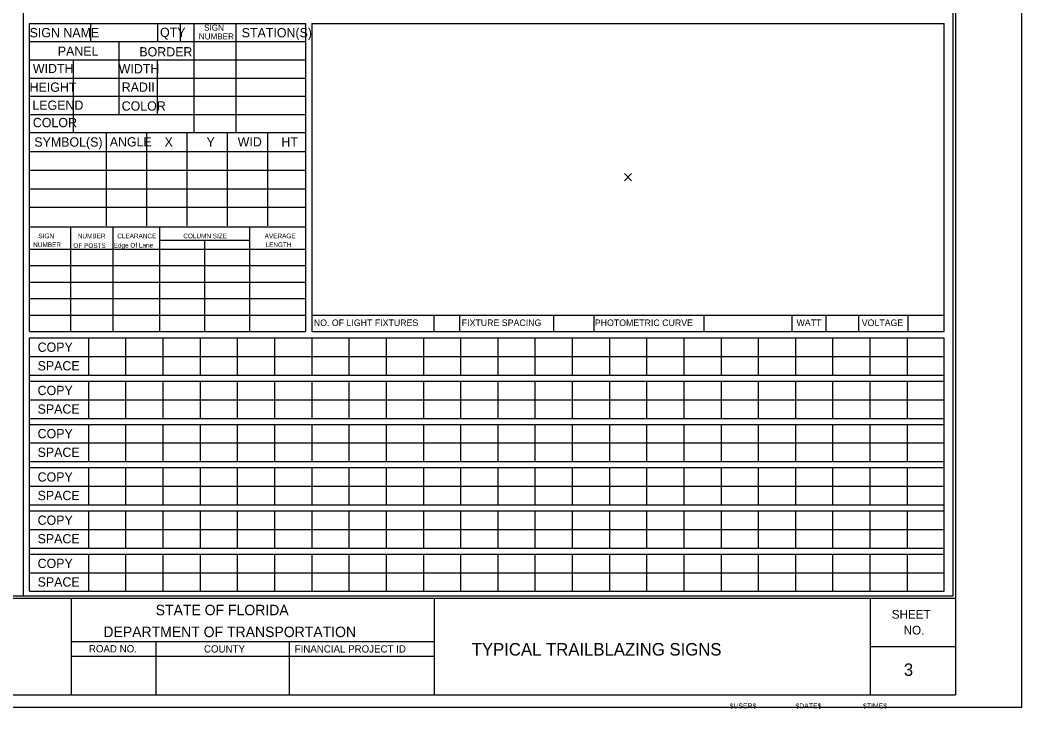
# Model space of a CAD drawing. Extents: x 17890628 to 17890754, y 17897693 to 17897992.
# Drawn here: x 17890707.16 to 17890727.42, y 17897874.78 to 17897888.7 of the extents above; entities that cross this region are included whole.
import ezdxf

# ---------------------------------------------------------------- set-up
doc = ezdxf.new("R2010")
doc.units = 0
for name, color, linetype in [('NonPlottingEle_dp', 7, 'Continuous'), ('PlotBorder_dp', 7, 'Continuous'), ('SheetBorder_dp', 7, 'Continuous'), ('SheetLines_dp', 7, 'Continuous'), ('SheetLinesMisc2_dp', 7, 'Continuous'), ('TextMinor', 7, 'Continuous'), ('TextMisc', 7, 'Continuous')]:
    doc.layers.add(name, color=color, linetype=linetype)

msp = doc.modelspace()

# ---------------------------------------------------------------- linework, layer by layer
at = {"layer": 'NonPlottingEle_dp'}
for p, q in [((17890719.378, 17897885.597), (17890719.524, 17897885.451)), ((17890719.378, 17897885.451), (17890719.524, 17897885.597))]:
    msp.add_line(p, q, dxfattribs=at)
at = {"layer": 'PlotBorder_dp'}
msp.add_lwpolyline([(17890687.002, 17897874.814), (17890727.417, 17897874.814), (17890727.417, 17897900.777), (17890687.002, 17897900.777)], close=True, dxfattribs=at)
at = {"layer": 'SheetBorder_dp'}
for p, q in [((17890726.07, 17897900.533), (17890726.07, 17897875.059)), ((17890688.35, 17897877.018), (17890726.07, 17897877.018)), ((17890688.35, 17897875.059), (17890726.07, 17897875.059))]:
    msp.add_line(p, q, dxfattribs=at)
at = {"layer": 'SheetLines_dp'}
for p, q in [((17890708.19, 17897877.018), (17890708.19, 17897875.059)), ((17890715.538, 17897875.059), (17890715.538, 17897877.018)), ((17890724.356, 17897875.059), (17890724.356, 17897877.018)), ((17890708.19, 17897876.137), (17890715.538, 17897876.137)), ((17890709.904, 17897876.137), (17890709.904, 17897875.059)), ((17890712.598, 17897876.137), (17890712.598, 17897875.059)), ((17890724.356, 17897876.039), (17890726.07, 17897876.039)), ((17890708.19, 17897875.843), (17890715.538, 17897875.843))]:
    msp.add_line(p, q, dxfattribs=at)
at = {"layer": 'SheetLinesMisc2_dp'}
for p, q in [((17890707.222, 17897900.475), (17890707.222, 17897877.063)), ((17890726.026, 17897877.063), (17890726.026, 17897900.474)), ((17890707.351, 17897882.404), (17890707.351, 17897888.634)), ((17890707.351, 17897888.634), (17890712.927, 17897888.634)), ((17890708.58, 17897888.634), (17890708.58, 17897888.266)), ((17890709.935, 17897888.634), (17890709.935, 17897888.266)), ((17890710.398, 17897888.634), (17890710.398, 17897888.266)), ((17890710.674, 17897888.634), (17890710.674, 17897886.426)), ((17890711.523, 17897888.634), (17890711.523, 17897886.426)), ((17890712.927, 17897888.634), (17890712.927, 17897882.404)), ((17890713.055, 17897888.634), (17890725.847, 17897888.634)), ((17890713.055, 17897888.634), (17890713.055, 17897882.413)), ((17890725.847, 17897882.413), (17890725.847, 17897888.635)), ((17890707.351, 17897888.266), (17890712.927, 17897888.266)), ((17890709.153, 17897888.266), (17890709.153, 17897886.79)), ((17890707.351, 17897887.898), (17890712.927, 17897887.898)), ((17890708.232, 17897887.898), (17890708.232, 17897886.426)), ((17890709.931, 17897887.894), (17890709.931, 17897886.79)), ((17890707.351, 17897887.53), (17890712.927, 17897887.53)), ((17890707.351, 17897887.162), (17890712.927, 17897887.162)), ((17890707.351, 17897886.794), (17890709.419, 17897886.794)), ((17890709.153, 17897886.79), (17890710.674, 17897886.79)), ((17890710.674, 17897886.794), (17890712.927, 17897886.794)), ((17890707.351, 17897886.426), (17890712.927, 17897886.426)), ((17890708.899, 17897886.419), (17890708.899, 17897884.54)), ((17890709.714, 17897886.419), (17890709.714, 17897884.54)), ((17890710.529, 17897886.419), (17890710.529, 17897884.54)), ((17890711.344, 17897886.419), (17890711.344, 17897884.54)), ((17890712.159, 17897886.419), (17890712.159, 17897884.54)), ((17890707.352, 17897886.043), (17890712.927, 17897886.043)), ((17890707.352, 17897885.667), (17890712.927, 17897885.667)), ((17890707.352, 17897885.292), (17890712.927, 17897885.292)), ((17890707.352, 17897884.916), (17890712.927, 17897884.916)), ((17890707.351, 17897884.522), (17890712.927, 17897884.522)), ((17890708.178, 17897884.522), (17890708.178, 17897882.404)), ((17890709.033, 17897884.522), (17890709.033, 17897882.404)), ((17890709.978, 17897884.522), (17890709.978, 17897882.404)), ((17890711.796, 17897884.522), (17890711.796, 17897882.404)), ((17890709.978, 17897884.253), (17890711.795, 17897884.253)), ((17890710.891, 17897884.253), (17890710.891, 17897882.404)), ((17890707.351, 17897884.073), (17890712.927, 17897884.073)), ((17890707.351, 17897883.739), (17890712.927, 17897883.739)), ((17890707.351, 17897883.405), (17890712.927, 17897883.405)), ((17890707.351, 17897883.071), (17890712.927, 17897883.071)), ((17890707.351, 17897882.738), (17890712.927, 17897882.738)), ((17890713.055, 17897882.738), (17890725.847, 17897882.738)), ((17890715.526, 17897882.738), (17890715.526, 17897882.404)), ((17890716.044, 17897882.738), (17890716.044, 17897882.404)), ((17890717.948, 17897882.738), (17890717.948, 17897882.404)), ((17890718.759, 17897882.738), (17890718.759, 17897882.404)), ((17890720.986, 17897882.738), (17890720.986, 17897882.404)), ((17890722.764, 17897882.738), (17890722.764, 17897882.404)), ((17890723.45, 17897882.738), (17890723.45, 17897882.404)), ((17890724.112, 17897882.738), (17890724.112, 17897882.404)), ((17890725.108, 17897882.738), (17890725.108, 17897882.404)), ((17890707.351, 17897882.404), (17890712.927, 17897882.404)), ((17890713.055, 17897882.413), (17890713.055, 17897882.404)), ((17890713.055, 17897882.404), (17890725.847, 17897882.404)), ((17890725.847, 17897882.404), (17890725.847, 17897882.413)), ((17890707.35, 17897882.276), (17890725.847, 17897882.276)), ((17890707.35, 17897877.154), (17890707.35, 17897882.276)), ((17890708.541, 17897882.276), (17890708.541, 17897881.524)), ((17890709.293, 17897882.276), (17890709.293, 17897881.524)), ((17890710.046, 17897882.276), (17890710.046, 17897881.524)), ((17890710.798, 17897882.276), (17890710.798, 17897881.524)), ((17890711.551, 17897882.276), (17890711.551, 17897881.524)), ((17890712.303, 17897882.276), (17890712.303, 17897881.524)), ((17890713.055, 17897882.276), (17890713.055, 17897881.524)), ((17890713.808, 17897882.276), (17890713.808, 17897881.524)), ((17890714.56, 17897882.276), (17890714.56, 17897881.524)), ((17890715.313, 17897882.276), (17890715.313, 17897881.524)), ((17890716.065, 17897882.276), (17890716.065, 17897881.524)), ((17890716.817, 17897882.276), (17890716.817, 17897881.524)), ((17890717.57, 17897882.276), (17890717.57, 17897881.524)), ((17890718.322, 17897882.276), (17890718.322, 17897881.524)), ((17890719.075, 17897882.276), (17890719.075, 17897881.524)), ((17890719.827, 17897882.276), (17890719.827, 17897881.524)), ((17890720.58, 17897882.276), (17890720.58, 17897881.524)), ((17890721.332, 17897882.276), (17890721.332, 17897881.524)), ((17890722.084, 17897882.276), (17890722.084, 17897881.524)), ((17890722.837, 17897882.276), (17890722.837, 17897881.524)), ((17890723.589, 17897882.276), (17890723.589, 17897881.524)), ((17890724.342, 17897882.276), (17890724.342, 17897881.524)), ((17890725.094, 17897882.276), (17890725.094, 17897881.524)), ((17890725.847, 17897877.154), (17890725.847, 17897882.276)), ((17890707.35, 17897881.9), (17890725.847, 17897881.9)), ((17890707.35, 17897881.524), (17890725.847, 17897881.524)), ((17890707.35, 17897881.402), (17890725.847, 17897881.402)), ((17890708.541, 17897881.402), (17890708.541, 17897880.65)), ((17890709.293, 17897881.402), (17890709.293, 17897880.65)), ((17890710.046, 17897881.402), (17890710.046, 17897880.65)), ((17890710.798, 17897881.402), (17890710.798, 17897880.65)), ((17890711.551, 17897881.402), (17890711.551, 17897880.65)), ((17890712.303, 17897881.402), (17890712.303, 17897880.65)), ((17890713.055, 17897881.402), (17890713.055, 17897880.65)), ((17890713.808, 17897881.402), (17890713.808, 17897880.65)), ((17890714.56, 17897881.402), (17890714.56, 17897880.65)), ((17890715.313, 17897881.402), (17890715.313, 17897880.65)), ((17890716.065, 17897881.402), (17890716.065, 17897880.65)), ((17890716.817, 17897881.402), (17890716.817, 17897880.65)), ((17890717.57, 17897881.402), (17890717.57, 17897880.65)), ((17890718.322, 17897881.402), (17890718.322, 17897880.65)), ((17890719.075, 17897881.402), (17890719.075, 17897880.65)), ((17890719.827, 17897881.402), (17890719.827, 17897880.65)), ((17890720.58, 17897881.402), (17890720.58, 17897880.65)), ((17890721.332, 17897881.402), (17890721.332, 17897880.65)), ((17890722.084, 17897881.402), (17890722.084, 17897880.65)), ((17890722.837, 17897881.402), (17890722.837, 17897880.65)), ((17890723.589, 17897881.402), (17890723.589, 17897880.65)), ((17890724.342, 17897881.402), (17890724.342, 17897880.65)), ((17890725.094, 17897881.402), (17890725.094, 17897880.65)), ((17890707.35, 17897881.026), (17890725.847, 17897881.026)), ((17890707.35, 17897880.65), (17890725.847, 17897880.65)), ((17890707.35, 17897880.527), (17890725.847, 17897880.527)), ((17890708.541, 17897880.527), (17890708.541, 17897879.776)), ((17890709.293, 17897880.527), (17890709.293, 17897879.776)), ((17890710.046, 17897880.527), (17890710.046, 17897879.776)), ((17890710.798, 17897880.527), (17890710.798, 17897879.776)), ((17890711.551, 17897880.527), (17890711.551, 17897879.776)), ((17890712.303, 17897880.527), (17890712.303, 17897879.776)), ((17890713.055, 17897880.527), (17890713.055, 17897879.776)), ((17890713.808, 17897880.527), (17890713.808, 17897879.776)), ((17890714.56, 17897880.527), (17890714.56, 17897879.776)), ((17890715.313, 17897880.527), (17890715.313, 17897879.776)), ((17890716.065, 17897880.527), (17890716.065, 17897879.776)), ((17890716.817, 17897880.527), (17890716.817, 17897879.776)), ((17890717.57, 17897880.527), (17890717.57, 17897879.776)), ((17890718.322, 17897880.527), (17890718.322, 17897879.776)), ((17890719.075, 17897880.527), (17890719.075, 17897879.776)), ((17890719.827, 17897880.527), (17890719.827, 17897879.776)), ((17890720.58, 17897880.527), (17890720.58, 17897879.776)), ((17890721.332, 17897880.527), (17890721.332, 17897879.776)), ((17890722.084, 17897880.527), (17890722.084, 17897879.776)), ((17890722.837, 17897880.527), (17890722.837, 17897879.776)), ((17890723.589, 17897880.527), (17890723.589, 17897879.776)), ((17890724.342, 17897880.527), (17890724.342, 17897879.776)), ((17890725.094, 17897880.527), (17890725.094, 17897879.776)), ((17890707.35, 17897880.152), (17890725.847, 17897880.152)), ((17890707.35, 17897879.776), (17890725.847, 17897879.776)), ((17890707.35, 17897879.654), (17890725.847, 17897879.654)), ((17890708.541, 17897879.654), (17890708.541, 17897878.902)), ((17890709.293, 17897879.654), (17890709.293, 17897878.902)), ((17890710.046, 17897879.654), (17890710.046, 17897878.902)), ((17890710.798, 17897879.654), (17890710.798, 17897878.902)), ((17890711.551, 17897879.654), (17890711.551, 17897878.902)), ((17890712.303, 17897879.654), (17890712.303, 17897878.902)), ((17890713.055, 17897879.654), (17890713.055, 17897878.902)), ((17890713.808, 17897879.654), (17890713.808, 17897878.902)), ((17890714.56, 17897879.654), (17890714.56, 17897878.902)), ((17890715.313, 17897879.654), (17890715.313, 17897878.902)), ((17890716.065, 17897879.654), (17890716.065, 17897878.902)), ((17890716.817, 17897879.654), (17890716.817, 17897878.902)), ((17890717.57, 17897879.654), (17890717.57, 17897878.902)), ((17890718.322, 17897879.654), (17890718.322, 17897878.902)), ((17890719.075, 17897879.654), (17890719.075, 17897878.902)), ((17890719.827, 17897879.654), (17890719.827, 17897878.902)), ((17890720.58, 17897879.654), (17890720.58, 17897878.902)), ((17890721.332, 17897879.654), (17890721.332, 17897878.902)), ((17890722.084, 17897879.654), (17890722.084, 17897878.902)), ((17890722.837, 17897879.654), (17890722.837, 17897878.902)), ((17890723.589, 17897879.654), (17890723.589, 17897878.902)), ((17890724.342, 17897879.654), (17890724.342, 17897878.902)), ((17890725.094, 17897879.654), (17890725.094, 17897878.902)), ((17890707.35, 17897879.278), (17890725.847, 17897879.278)), ((17890707.35, 17897878.902), (17890725.847, 17897878.902)), ((17890707.35, 17897878.779), (17890725.847, 17897878.779)), ((17890708.541, 17897878.779), (17890708.541, 17897878.028)), ((17890709.293, 17897878.779), (17890709.293, 17897878.028)), ((17890710.046, 17897878.779), (17890710.046, 17897878.028)), ((17890710.798, 17897878.779), (17890710.798, 17897878.028)), ((17890711.551, 17897878.779), (17890711.551, 17897878.028)), ((17890712.303, 17897878.779), (17890712.303, 17897878.028)), ((17890713.055, 17897878.779), (17890713.055, 17897878.028)), ((17890713.808, 17897878.779), (17890713.808, 17897878.028)), ((17890714.56, 17897878.779), (17890714.56, 17897878.028)), ((17890715.313, 17897878.779), (17890715.313, 17897878.028)), ((17890716.065, 17897878.779), (17890716.065, 17897878.028)), ((17890716.817, 17897878.779), (17890716.817, 17897878.028)), ((17890717.57, 17897878.779), (17890717.57, 17897878.028)), ((17890718.322, 17897878.779), (17890718.322, 17897878.028)), ((17890719.075, 17897878.779), (17890719.075, 17897878.028)), ((17890719.827, 17897878.779), (17890719.827, 17897878.028)), ((17890720.58, 17897878.779), (17890720.58, 17897878.028)), ((17890721.332, 17897878.779), (17890721.332, 17897878.028)), ((17890722.084, 17897878.779), (17890722.084, 17897878.028)), ((17890722.837, 17897878.779), (17890722.837, 17897878.028)), ((17890723.589, 17897878.779), (17890723.589, 17897878.028)), ((17890724.342, 17897878.779), (17890724.342, 17897878.028)), ((17890725.094, 17897878.779), (17890725.094, 17897878.028)), ((17890707.35, 17897878.404), (17890725.847, 17897878.404)), ((17890707.35, 17897878.028), (17890725.847, 17897878.028)), ((17890707.35, 17897877.905), (17890725.847, 17897877.905)), ((17890708.541, 17897877.905), (17890708.541, 17897877.154)), ((17890709.293, 17897877.905), (17890709.293, 17897877.154)), ((17890710.046, 17897877.905), (17890710.046, 17897877.154)), ((17890710.798, 17897877.905), (17890710.798, 17897877.154)), ((17890711.551, 17897877.905), (17890711.551, 17897877.154)), ((17890712.303, 17897877.905), (17890712.303, 17897877.154)), ((17890713.055, 17897877.905), (17890713.055, 17897877.154)), ((17890713.808, 17897877.905), (17890713.808, 17897877.154)), ((17890714.56, 17897877.905), (17890714.56, 17897877.154)), ((17890715.313, 17897877.905), (17890715.313, 17897877.154)), ((17890716.065, 17897877.905), (17890716.065, 17897877.154)), ((17890716.817, 17897877.905), (17890716.817, 17897877.154)), ((17890717.57, 17897877.905), (17890717.57, 17897877.154)), ((17890718.322, 17897877.905), (17890718.322, 17897877.154)), ((17890719.075, 17897877.905), (17890719.075, 17897877.154)), ((17890719.827, 17897877.905), (17890719.827, 17897877.154)), ((17890720.58, 17897877.905), (17890720.58, 17897877.154)), ((17890721.332, 17897877.905), (17890721.332, 17897877.154)), ((17890722.084, 17897877.905), (17890722.084, 17897877.154)), ((17890722.837, 17897877.905), (17890722.837, 17897877.154)), ((17890723.589, 17897877.905), (17890723.589, 17897877.154)), ((17890724.342, 17897877.905), (17890724.342, 17897877.154)), ((17890725.094, 17897877.905), (17890725.094, 17897877.154)), ((17890707.35, 17897877.53), (17890725.847, 17897877.53)), ((17890707.35, 17897877.154), (17890725.847, 17897877.154)), ((17890688.417, 17897877.063), (17890726.026, 17897877.063))]:
    msp.add_line(p, q, dxfattribs=at)

# ---------------------------------------------------------------- texts
at = {"layer": 'TextMinor'}
for s, height, p in [('SIGN NAME', 0.1875, (17890707.351, 17897888.353)), ('QTY', 0.1875, (17890709.989, 17897888.359)), ('SIGN', 0.1225, (17890710.879, 17897888.487)), ('STATION(S)', 0.1875, (17890711.64, 17897888.352)), ('NUMBER', 0.1225, (17890710.773, 17897888.309)), ('PANEL', 0.1875, (17890707.921, 17897887.979)), ('BORDER', 0.1875, (17890709.57, 17897887.966)), ('WIDTH', 0.1875, (17890707.417, 17897887.628)), ('WIDTH', 0.1875, (17890709.153, 17897887.625)), ('HEIGHT', 0.1875, (17890707.351, 17897887.251)), ('RADII', 0.1875, (17890709.214, 17897887.252)), ('LEGEND', 0.1875, (17890707.407, 17897886.887)), ('COLOR', 0.1875, (17890709.213, 17897886.871)), ('COLOR', 0.1875, (17890707.417, 17897886.536)), ('SYMBOL(S)', 0.1875, (17890707.447, 17897886.143)), ('ANGLE', 0.1875, (17890708.971, 17897886.146)), ('X', 0.187, (17890710.081, 17897886.143)), ('Y', 0.187, (17890710.928, 17897886.143)), ('WID', 0.1875, (17890711.559, 17897886.146)), ('HT', 0.1875, (17890712.442, 17897886.143)), ('NUMBER', 0.0937, (17890707.424, 17897884.113)), ('SIGN', 0.0937, (17890707.529, 17897884.291)), ('NUMBER', 0.0937, (17890708.325, 17897884.29)), ('CLEARANCE', 0.0937, (17890709.123, 17897884.29)), ('COLUMN SIZE', 0.09374, (17890710.459, 17897884.29)), ('AVERAGE', 0.0937, (17890712.104, 17897884.29)), ('LENGTH', 0.0937, (17890712.121, 17897884.113)), ('OF POSTS', 0.0937, (17890708.237, 17897884.095)), ('Edge Of Lane', 0.09374, (17890709.051, 17897884.102)), ('NO. OF LIGHT FIXTURES', 0.13286, (17890713.098, 17897882.516)), ('FIXTURE SPACING', 0.13286, (17890716.09, 17897882.516)), ('PHOTOMETRIC CURVE', 0.13286, (17890718.78, 17897882.516)), ('WATT', 0.1329, (17890722.859, 17897882.516)), ('VOLTAGE', 0.1329, (17890724.178, 17897882.516)), ('COPY', 0.1875, (17890707.513, 17897881.995)), ('SPACE', 0.1875, (17890707.513, 17897881.619)), ('COPY', 0.1875, (17890707.513, 17897881.12)), ('SPACE', 0.1875, (17890707.513, 17897880.745)), ('COPY', 0.1875, (17890707.513, 17897880.247)), ('SPACE', 0.1875, (17890707.513, 17897879.871)), ('COPY', 0.1875, (17890707.513, 17897879.372)), ('SPACE', 0.1875, (17890707.513, 17897878.997)), ('COPY', 0.1875, (17890707.513, 17897878.498)), ('SPACE', 0.1875, (17890707.513, 17897878.123)), ('COPY', 0.1875, (17890707.513, 17897877.624)), ('SPACE', 0.1875, (17890707.513, 17897877.249))]:
    msp.add_text(s, height=height, dxfattribs=at).set_placement(p)
at = {"layer": 'TextMisc'}
for s, height, p in [('STATE OF FLORIDA', 0.21163, (17890709.901, 17897876.67)), ('DEPARTMENT OF TRANSPORTATION', 0.21163, (17890708.843, 17897876.228)), ('TYPICAL TRAILBLAZING SIGNS', 0.25259, (17890716.292, 17897875.855)), ('ROAD NO.', 0.147, (17890708.55, 17897875.919)), ('COUNTY', 0.147, (17890710.877, 17897875.916)), ('FINANCIAL PROJECT ID', 0.14696, (17890712.711, 17897875.916)), ('3', 0.253, (17890725.03, 17897875.443)), ('$USER$', 0.101, (17890721.504, 17897874.786)), ('$DATE$', 0.101, (17890722.837, 17897874.786)), ('$TIME$', 0.101, (17890724.202, 17897874.786))]:
    msp.add_text(s, height=height, dxfattribs=at).set_placement(p)
for s, p in [('SHEET', (17890724.784, 17897876.6)), ('NO.', (17890725.024, 17897876.281))]:
    msp.add_text(s, height=0.1764, rotation=359.8607, dxfattribs=at).set_placement(p)

doc.saveas('drawing.dxf')
